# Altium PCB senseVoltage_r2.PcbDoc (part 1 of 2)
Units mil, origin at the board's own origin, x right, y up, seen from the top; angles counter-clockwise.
Board outline 4100 x 1400 mil, 2 copper layers (Top Layer, Bottom Layer), stack 62 mil thick; 83 components, 46 nets, 184 pads, 26 vias.
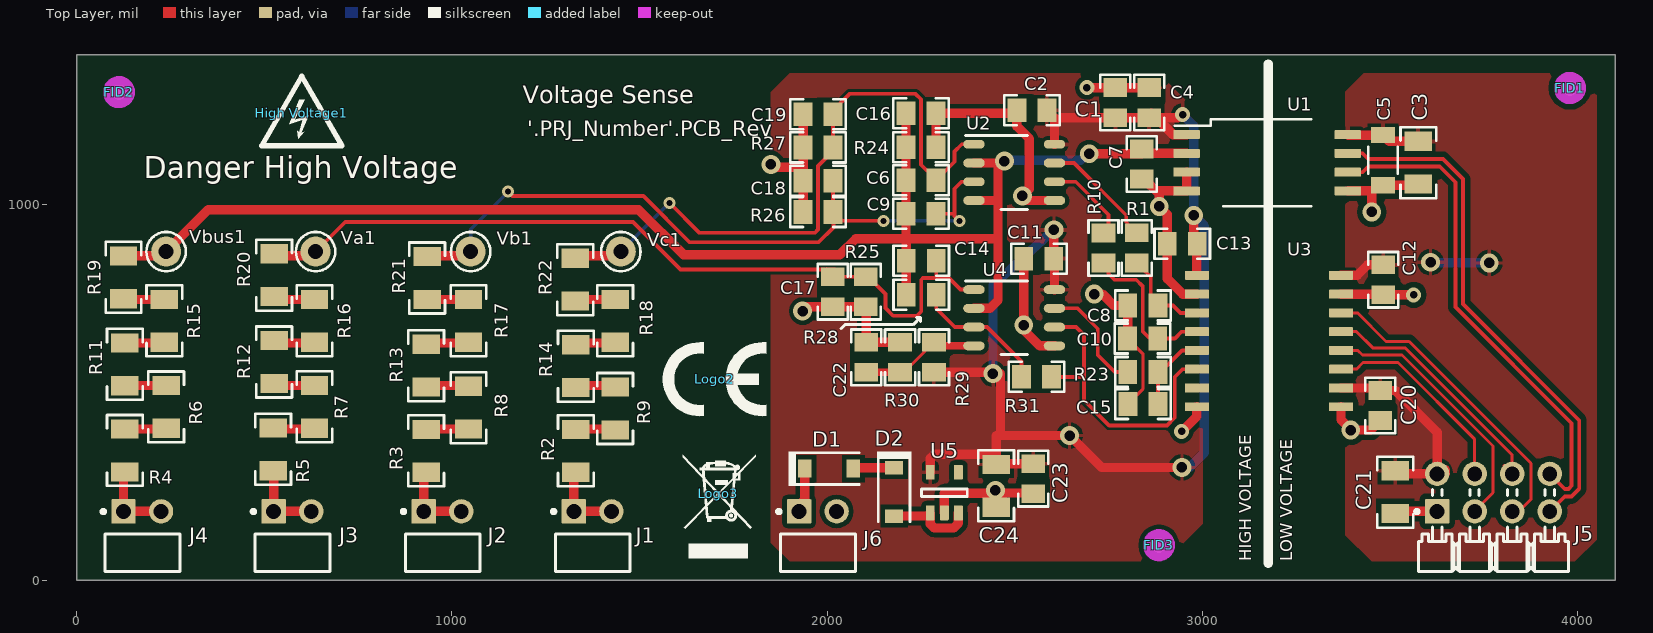
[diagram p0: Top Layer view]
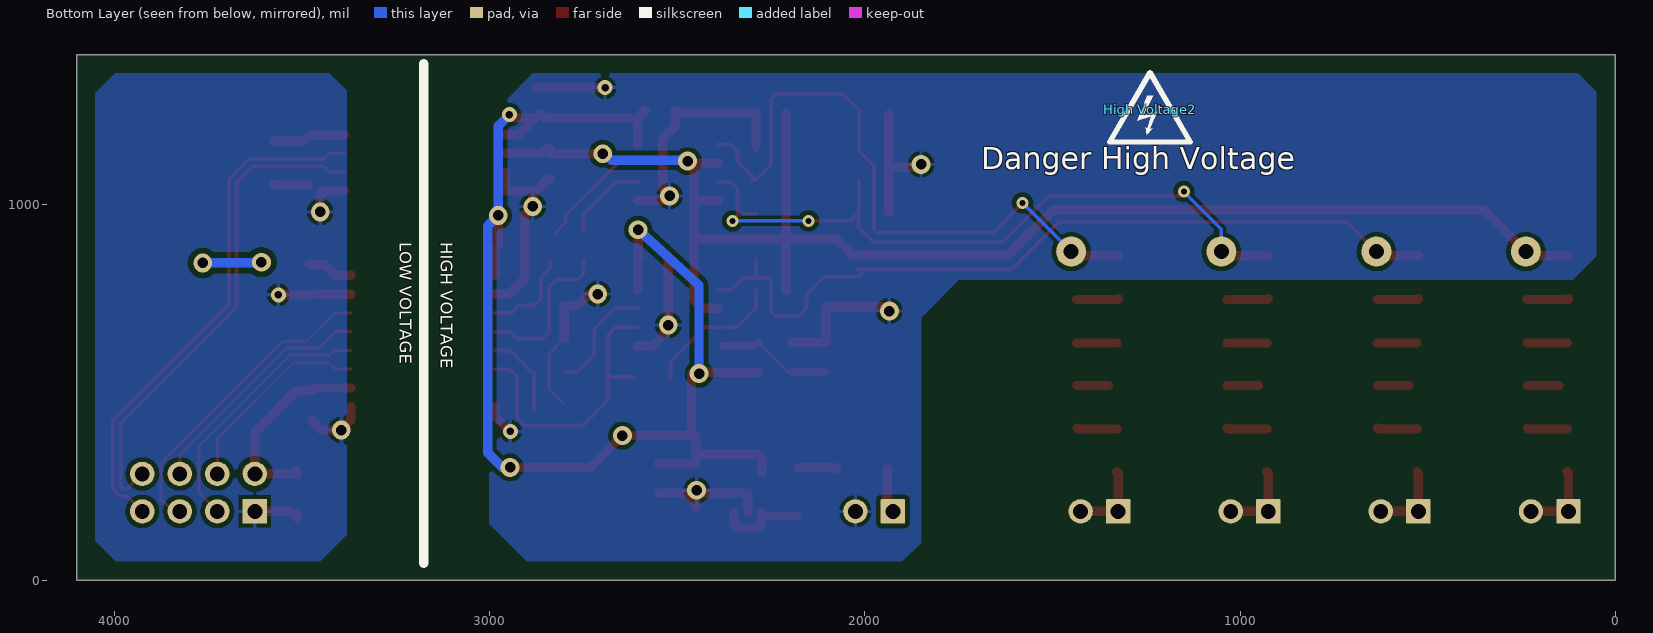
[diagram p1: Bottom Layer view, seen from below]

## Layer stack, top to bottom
Top Solder: solder mask 0.4, Solder Resist, Dk 3.5
Top Layer: signal copper 1.4
Dielectric1: core 59.2, FR-4, Dk 4.8
Bottom Layer: signal copper 1.4
Bottom Solder: solder mask 0.4, Solder Resist, Dk 3.5

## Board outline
0,0 4100,0 4100,1400 0,1400

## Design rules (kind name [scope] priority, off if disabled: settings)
AcuteAngle [All] p1: minimum=4.50000000000000E+0001 checktracksonly=FALSE
AssemblyTestPointUsage [All] p1: valid=2
BoardOutlineClearance BoardOutlineClearance_MountingHoles [OnCopper and InComponentClass('Mounting Holes')] p1: gap=39.37 ignorepadtopadclearanceinfootprint=FALSE
BoardOutlineClearance BoardOutlineClearance_Poly [OnCopper and IsPoly] p2: gap=25 ignorepadtopadclearanceinfootprint=FALSE
BoardOutlineClearance [OnCopper and Not InComponentClass('Logo') and not InComponentClass('FiducialMark') and not InRegion(1000,500,4000,800) and not InPoly and Not IsKeepOut] p3: gap=60 ignorepadtopadclearanceinfootprint=FALSE except(25: Poly-CutoutEdge Text-CutoutEdge; 50: Arc-CutoutEdge Track-CutoutEdge SMDPad-CutoutEdge THPad-CutoutEdge Via-CutoutEdge Fill-CutoutEdge Region-CutoutEdge)
Clearance Clearance_Keepouts [((IsTrack Or IsArc) And Not InPoly) And IsFree and IsKeepOut vs ((IsTrack Or IsArc) And Not InPoly) And IsFree and IsKeepOut] p1: gap=0 ignorepadtopadclearanceinfootprint=FALSE
Clearance Clearance_Small_Vias [(HoleDiameter = 10)] p2: gap=8 ignorepadtopadclearanceinfootprint=TRUE
Clearance Clearance_TP_blue_wires [HasFootprint('TP_H045P075')] p3: gap=15 ignorepadtopadclearanceinfootprint=TRUE
Clearance Clearance_3V3 [InNet('3V3')] p4: gap=15 ignorepadtopadclearanceinfootprint=TRUE
Clearance Clearance_10_mil_traces [Width = 10] p5: gap=8 ignorepadtopadclearanceinfootprint=TRUE
Clearance Clearance_Poly [InPolygon] p6: gap=12 ignorepadtopadclearanceinfootprint=TRUE
Clearance Clearance_FiducialMark [IsKeepOut and InComponentClass('FiducialMark') vs IsPad and InComponentClass('FiducialMark')] p7: gap=0 ignorepadtopadclearanceinfootprint=FALSE
Clearance [All] p8: gap=7.87 ignorepadtopadclearanceinfootprint=TRUE
ComponentClearance ComponentClearance_MountingHoles_FiducialMarks [InComponentClass('Mounting Holes') vs InComponentClass('FiducialMark')] p1: gap=50 collisioncheckmode=3 verticalgap=10 showdistances=FALSE
ComponentClearance ComponentClearance_Shunt [InComponentClass('Header') vs InComponentClass('Shunt')] p2: gap=0 collisioncheckmode=3 verticalgap=0 showdistances=FALSE
ComponentClearance ComponentClearance_Logo [InComponentClass('Logo')] p3: gap=50 collisioncheckmode=3 verticalgap=10 showdistances=FALSE
ComponentClearance ComponentClearance_ScrewToNut [(HasFootprint('NY PMS 440 0025 PH')) vs (HasFootprint('Keystone_1902C'))] p4: gap=5 collisioncheckmode=3 verticalgap=10 showdistances=FALSE
ComponentClearance ComponentClearance_MountingHoles [InComponentClass('Mounting Holes')] p5: gap=250 collisioncheckmode=3 verticalgap=100000 showdistances=FALSE
ComponentClearance ComponentClearance_SmallPassives [HasFootprint('0201*') or HasFootprint('0402*') or HasFootprint('0508') or HasFootprint('0603*') or HasFootprint('0612') or HasFootprint('0805*') or HasFootprint('0815*') or HasFootprint('0830*') or HasFootprint('1206*') or HasFootprint('1210*') or HasFootprint('1808*') or HasFootprint('1812*') or HasFootprint('1825*') or HasFootprint('2010*') or HasFootprint('2220*') or HasFootprint('2225*') or HasFootprint('2512*') or HasFootprint('2728*') or HasFootprint('3518*') vs HasFootprint('0201*') or HasFootprint('0402*') or HasFootprint('0508') or HasFootprint('0603*') or HasFootprint('0612') or HasFootprint('0805*') or HasFootprint('0815*') or HasFootprint('0830*') or HasFootprint('1206*') or HasFootprint('1210*') or HasFootprint('1808*') or HasFootprint('1812*') or HasFootprint('1825*') or HasFootprint('2010*') or HasFootprint('2220*') or HasFootprint('2225*') or HasFootprint('2512*') or HasFootprint('2728*') or HasFootprint('3518*')] p6: gap=14.96 collisioncheckmode=3 verticalgap=10 showdistances=FALSE
ComponentClearance ComponentClearance_THtoSMT [IsThruComponent vs IsSMTComponent] p7: gap=20 collisioncheckmode=3 verticalgap=30 showdistances=FALSE
ComponentClearance ComponentClearance_TestPoint [HasFootprint('TP_H045P075')] p8: gap=0 collisioncheckmode=3 verticalgap=30 showdistances=FALSE
ComponentClearance ComponentClearance_THtoTH [IsThruComponent vs IsThruComponent] p9: gap=30 collisioncheckmode=3 verticalgap=30 showdistances=FALSE
ComponentClearance [All] p10: gap=30 collisioncheckmode=3 verticalgap=10 showdistances=FALSE
DiffPairsRouting [All] p1: maxlimit=100 minlimit=10 mostfreqgap=10 toplayer_minwidth=10 toplayer_maxwidth=15 toplayer_prefwidth=10 bottomlayer_minwidth=10 bottomlayer_maxwidth=15 bottomlayer_prefwidth=10 maxuncoupledlength=1000
FabricationTestPointUsage TestPointUsage [All] p1: valid=2 allowmultiple=FALSE
FabricationTestpoint Testpoint [All] p1: side=3 testpointundercomponent=TRUE minsize=40 maxsize=100 preferedsize=60 minholesize=0 maxholesize=40 preferedholesize=32 testpointgrid=1 allowsidetop=TRUE allowsidebottom=TRUE usegrid=TRUE gridtolerance=0.01
FanoutControl Fanout_LCC [IsLCC] p1: bgadir=Out bgaviamode=Centered fanoutstyle=Auto fanoutdirection=Alternating viagrid=1 // Fanout_LCC (Default Rule)
FanoutControl Fanout_BGA [IsBGA] p2: bgadir=Out bgaviamode=Centered fanoutstyle=Auto fanoutdirection=Alternating viagrid=1 // Fanout_BGA (Default Rule)
FanoutControl Fanout_Default [All] p4: bgadir=Out bgaviamode=Centered fanoutstyle=Auto fanoutdirection=Alternating viagrid=1 // Fanout_Default (Default Rule)
FanoutControl Fanout_Small [(CompPinCount < 5)] p5: bgadir=Out bgaviamode=Centered fanoutstyle=Auto fanoutdirection=OutThenIn viagrid=1 // Fanout_Small (Default Rule)
HoleSize [All] p1: absolutevalues=TRUE maxlimit=251 minlimit=7.87 maxpercent=80.000 minpercent=20.000
MinimumAnnularRing MinimumAnnularRing_ThermalPadVias [IsVia and InAnyComponent] p1: minimumring=5.91
MinimumAnnularRing [All] p2: minimumring=6
MinimumSolderMaskSliver MinimumSolderMaskSliver_Logo [InComponentClass('Logo') vs InComponentClass('Logo')] p1: minsoldermaskwidth=0.7
MinimumSolderMaskSliver [All] p2: minsoldermaskwidth=3.94
PlaneConnect [All] p1: planeconnectstyle=Relief reliefexpansion=10 reliefentries=4 reliefconductorwidth=10 reliefairgap=10
PolygonConnect [All] p1: connectstyle=Relief reliefconductorwidth=10 reliefentries=4 polygonreliefangle="90 Angle" airgapwidth=10
RoomDefinition RoomDefinition_2 [False vs False] p1: confinementstyle=ConfineIn formatcopy=TRUE lockcomponents=FALSE outline 1180,-285 815,-285 815,955 1180,955
RoomDefinition RoomDefinition_3 [InComponentClass('Room Definition 4') vs False] p2: confinementstyle=ConfineIn formatcopy=TRUE lockcomponents=FALSE outline 1208,-284 1558,-284 1558,966 1208,966
RoomDefinition RoomDefinition_1 [InComponentClass('Room Definition 2') vs False] p3: confinementstyle=ConfineIn formatcopy=TRUE lockcomponents=FALSE outline 408,-284 758,-284 758,966 408,966
RoomDefinition [InComponentClass('Room Definition 1') vs False] p4: confinementstyle=ConfineIn formatcopy=TRUE lockcomponents=FALSE outline 8,-284 358,-284 358,966 8,966
RoutingVias ThermalPadVias [IsVia and InAnyComponent] p1: holewidth=7.87 width=19.68 viastyle="Through Hole" minholewidth=7.87 minwidth=19.68 maxholewidth=12.99 maxwidth=23.62
RoutingVias [All] p2: holewidth=16 width=34 viastyle="Through Hole" minholewidth=7.87 minwidth=22 maxholewidth=40 maxwidth=65
SilkToBoardRegionClearance [Not ((IsComment or IsDesignator) And (Hide <> 'False')) and not InRegion(1000,500,4000,800)] p1:
SilkToSilkClearance SilkToSilkClearance_Pb-FreeLogo [(HasFootprint('Pb-Free_Overlay_Medium') OR HasFootprint('Pb-Free_Overlay_Small')) vs (HasFootprint('Pb-Free_Overlay_Medium') OR HasFootprint('Pb-Free_Overlay_Small'))] p1: silktosilkclearance=0
SilkToSilkClearance [All] p2: silktosilkclearance=3.94
SilkToSolderMaskClearance SilkToComponentPadClearance [(IsPad or IsFill or IsRegion) and InAnycomponent] p1: minsilkscreentomaskgap=5 clearancetoexposedcopper=TRUE
SilkToSolderMaskClearance "Silk to Solder Mask Opening" [All] p2: minsilkscreentomaskgap=3 clearancetoexposedcopper=FALSE
SolderMaskExpansion [All] p1: expansion=1.97
UnRoutedNet [All] p1: checkbadconnections=TRUE
Width [All] p1: maxlimit=100 minlimit=6 preferedwidth=10 checkconnectedcopper=TRUE
14 further rules are at their usual default settings.

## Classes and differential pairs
component class voltageSense_EVT: C1 C2 C3 C4 C5 C6 C7 C8 C9 C10 C11 C12 C13 C14 C15 C16 C17 C18 C19 C20 C21 C22 C23 C24 D1 D2 J1 J2 J3 J4 J5 J6 R1 R2 R3 R4 R5 R6 R7 R8 R9 R10 R11 R12 R13 R14 R15 R16 R17 R18 R19 R20 R21 R22 R23 R24 R25 R26 R27 R28 R29 R30 R31 U1 U2 U3 U4 U5 Va1 Vb1 Vbus1 Vc1
component class Header: J5
component class Hardware: FID1 FID2 FID3 "High Voltage1" "High Voltage2" Logo2 Logo3 ZZ1 ZZ2 ZZ3 ZZ4
component class FiducialMark: FID1 FID2 FID3
component class AssemblyNote: ZZ1 ZZ2 ZZ3 ZZ4
differential pair Vdc: +Vdc_P -Vdc_N

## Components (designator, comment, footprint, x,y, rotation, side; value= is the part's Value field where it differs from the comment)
C1 "GRM219R71C225KE15" 0805_HV 2767.56,1271.99 r90 top value=2.2uF
C2 "08053C224JAT2A" 0805_HV 2545.36,1251.65 r0 top value=0.22uF
C3 "GRM31MR71C225KA35L" 1206 3575,1112.09 r90 top value=2.2uF
C4 "08053C224JAT2A" 0805_HV 2857.85,1271.99 r90 top value=0.22uF
C5 "C1206H104J3GACTU" 1206_190 3480.78,1118.5 r90 top value=0.1uF
C6 "08051A150JAT2A" 0805_HV 2249.86,1065.2 r180 top value=15pF
C7 "08051A100CAT2A" 0805_HV 2837.85,1108.49 r270 top value=10pF
C8 "08051A101JAT2A" 0805_HV 2840.95,731.4 r180 top value=100pF
C9 "08051A150JAT2A" 0805_HV 2249.86,975.68 r180 top value=15pF
C10 "08051A101JAT2A" 0805_HV 2840.36,643.68 r180 top value=100pF
C11 "08053C224JAT2A" 0805_HV 2563.81,855.84 r0 top value=0.22uF
C12 "GRM219R71C104KA01D" 0805_HV 3481.58,800 r270 top value=0.1uF
C13 "GRM219R71C104KA01D" 0805_HV 2946,895.58 r180 top value=0.1uF
C14 "08051A150JAT2A" 0805_HV 2250.39,850.42 r180 top value=15pF
C15 "08051A101JAT2A" 0805_HV 2841.38,468.91 r180 top value=100pF
C16 "08053C224JAT2A" 0805_HV 2249.86,1243.74 r180 top value=0.22uF
C17 "08051A330JAT2A" 0805_HV 2015,768.2 r270 top value=33pF
C18 "08051A330JAT2A" 0805_HV 1975.59,1063.84 r180 top value=33pF
C19 "08051A330JAT2A" 0805_HV 1975.59,1241.49 r180 top value=33pF
C20 "GRM21BR70J106KE76L" 0805_HV 3473.12,465 r90 top value=10uF
C21 "1206YC104KAT2A" 1206 3513.32,234.06 r270 top value=0.1uF
C22 "08051A330JAT2A" 0805_HV 2104.05,593.42 r90 top value=33pF
C23 "GRM21BR70J106KE76L" 0805_HV 2549,270 r90 top value=10uF
C24 "1206YC104KAT2A" 1206 2450,251 r270 top value=0.1uF
D1 "MMSZ4687-HE3-08" SOD-123 2005,297 r0 top value=4.3V
D2 "MMSZ4687-HE3-08" SOD-123 2178,235 r270 top value=4.3V
FID1 "Fiducial" Fiducial10-20#1 3978.96,1310.98 r90 top
FID2 "Fiducial" Fiducial10-20#2 112.82,1300 r0 top
FID3 "Fiducial" Fiducial10-20#2 2883.67,92.88 r0 top
"High Voltage1" "DANGER HIGH VOLTAGE" IEC_HighVoltage_Small 600,1245 r0 top
"High Voltage2" "DANGER HIGH VOLTAGE" IEC_HighVoltage_Small 1240,1255 r180 bottom
J1 "TSW-102-08-G-S-RA" TSW-102-08-G-S-RA 1375,182.88 r0 top
J2 "TSW-102-08-G-S-RA" TSW-102-08-G-S-RA 975,182.88 r0 top
J3 "TSW-102-08-G-S-RA" TSW-102-08-G-S-RA 575,182.88 r0 top
J4 "TSW-102-08-G-S-RA" TSW-102-08-G-S-RA 175,182.88 r0 top
J5 "TSW-104-09-G-D-RA" Samtec_TSW-104-09-G-D-RA 3775,232.88 r0 top
J6 "TSW-102-08-G-S-RA" TSW-102-08-G-S-RA 1975,182.88 r0 top
Logo2 "CE Mark" CE_Mark_5mm 1700,535 r0 top
Logo3 "WEEE logo" WEEE_Minimum 1710,229.9 r0 top
R1 "PHT0805Y1001BGT200" 0805_HV 2824.67,885 r270 top value=1.00k
R2 "ERJ-8ENF2003V" 1206 1330.34,344.22 r270 top value=200k
R3 "ERJ-8ENF2003V" 1206 931.43,344.22 r270 top value=200k
R4 "ERJ-8ENF2003V" 1206 128.57,345.23 r270 top value=200k
R5 "ERJ-8ENF2003V" 1206 523.58,348.23 r270 top value=200k
R6 "ERJ-8ENF2003V" 1206 238.6,461.3 r270 top value=200k
R7 "ERJ-8ENF2003V" 1206 634,461.39 r270 top value=200k
R8 "ERJ-8ENF2003V" 1206 1044.24,459.33 r270 top value=200k
R9 "ERJ-8ENF2003V" 1206 1435,456.98 r270 top value=200k
R10 "PHT0805Y1001BGT200" 0805_HV 2735.98,885 r270 top value=1.00k
R11 "ERJ-8ENF2003V" 1206 128.57,574.58 r270 top value=200k
R12 "ERJ-8ENF2003V" 1206 526.26,580.99 r270 top value=200k
R13 "ERJ-8ENF2003V" 1206 931.43,571.15 r270 top value=200k
R14 "ERJ-8ENF2003V" 1206 1330.34,569.88 r270 top value=200k
R15 "ERJ-8ENF2003V" 1206 234,690.51 r270 top value=200k
R16 "ERJ-8ENF2003V" 1206 634,690.51 r270 top value=200k
R17 "ERJ-8ENF2003V" 1206 1044.24,690.72 r270 top value=200k
R18 "ERJ-8ENF2003V" 1206 1435,690.51 r270 top value=200k
R19 "ERJ-8ENF2003V" 1206 125,806.65 r270 top value=200k
R20 "ERJ-8ENF2003V" 1206 526.26,812.29 r270 top value=200k
R21 "ERJ-8ENF2003V" 1206 934.1,804.68 r270 top value=200k
R22 "ERJ-8ENF2003V" 1206 1328.67,800.19 r270 top value=200k
R23 "PHT0805Y1001BGT200" 0805_HV 2840.95,554.41 r0 top value=1.00k
R24 "RG2012P-302-B-T5" 0805_HV 2249.86,1153.35 r180 top value=3.00k
R25 "RG2012P-432-B-T5" 0805_HV 2103,768.2 r90 top value=4.30k
R26 "RG2012P-432-B-T5" 0805_HV 1975.59,980.54 r0 top value=4.30k
R27 "RG2012P-432-B-T5" 0805_HV 1975.59,1152.62 r0 top value=4.30k
R28 "RG2012P-302-B-T5" 0805_HV 2250.39,760 r180 top value=3.00k
R29 "RR1220P-3321-D-M" 0805_HV 2284.44,593.42 r270 top value=3.32k
R30 "RG2012P-3322-B-T5" 0805_HV 2194.05,593.42 r270 top value=33.2k
R31 "RR1220P-104-D" 0805_HV 2557.79,541.24 r180 top value=100k
U1 "AMC1311BDWVR" DWV0008A 3171.97,1111.83 r0 top
U2 "TLV3502AID" D0008A_N 2498.14,1086.18 r0 top
U3 "ISO7240CDWR" DW0016B_HV 3176.97,636.82 r0 top
U4 "TLV3502AID" D0008A_N 2498.09,698.92 r0 top
U5 "TLV71333PQDBVRQ1" DBV0005A_N 2312,233 r90 top
Va1 "5002" Keystone5002 636.76,875 r270 top
Vb1 "5002" Keystone5002 1050,875 r90 top
Vbus1 "5002" Keystone5002 238.6,875 r270 top
Vc1 "5002" Keystone5002 1450,875 r180 top
ZZ1 "This Assembly Note is for PCB labels only" AssemblyNoteLabel 155,5443 r0 top
ZZ2 "These assemblies are ESD sensitive, ESD precautions shall be observed." AssemblyNote 155,5334.11 r0 top
ZZ3 "These assemblies must be clean and free from flux and all contaminants. Use of no clean flux is not acceptable." AssemblyNote 155,5245.56 r0 top
ZZ4 "These assemblies must comply with workmanship standards IPC-A-610 Class 2, unless otherwise specified." AssemblyNote 155,5157 r0 top

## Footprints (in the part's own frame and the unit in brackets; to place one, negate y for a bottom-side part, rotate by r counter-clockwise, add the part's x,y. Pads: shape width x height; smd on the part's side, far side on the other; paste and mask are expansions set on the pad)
0805_HV [mil] "0805 with 30mil clearance between pads"
  rect 50x63 smd: 1(-40,0) 2(40,0)
  silkscreen extent -74,-40 74,40, body extent -43,-29 43,29, height 57
1206 [mm] "1206 from SM-752 data"
  rect 1.3x1.85 smd: 1(-1.45,0) 2(1.45,0)
  silkscreen extent -2.4,-1.21 2.4,1.21, body extent -1.7,-0.9 1.7,0.9, height 1.35
1206_190 [mm] "1206_190"
  rect 1.1x1.6 smd: 1(-1.7,0) 2(1.7,0)
  silkscreen extent -0.9,-1 0.9,1, body extent -1.75,-0.95 1.75,0.95, height 1.9
AssemblyNote [mil] "Assembly Note"
AssemblyNoteLabel [mil] "Assembly Note for PCB Labels"
CE_Mark_5mm [mil] "Minimum text height for CE Mark"
  silkscreen extent -138,-98 138,98
D0008A_N [mm] "SOIC, 8-Leads, Body 4.9x3.9mm, Pitch 1.27mm, IPC Medium Density"
  oval 1.45x0.6 smd: 1(-2.725,1.905) 2(-2.725,0.635) 3(-2.725,-0.635) 4(-2.725,-1.905) 5(2.725,-1.905) 6(2.725,-0.635) 7(2.725,0.635) 8(2.725,1.905)
  silkscreen extent -3.3,-2.5 0.9,2.5, body extent -3,-2.45 3,2.45, height 1.63
DBV0005A_N [mm] "SOT23, 5-Leads, Body 2.9x1.6mm, Pitch 0.95mm, Lead Span 2.8mm, IPC Medium Density"
  rrect17% 1x0.6 smd: 1(-1.375,0.95) 2(-1.375,0) 3(-1.375,-0.95) 4(1.375,-0.95) 5(1.375,0.95)
  silkscreen extent -0.25,-1.55 0.25,1.55, body extent -1.42,-1.46 1.42,1.46, height 1.09
DW0016B_HV [mm] "SOIC-16, HV/isolation option"
  rrect17% 1.65x0.6 smd: 1(-4.875,4.445) 2(-4.875,3.175) 3(-4.875,1.905) 4(-4.875,0.635) 5(-4.875,-0.635) 6(-4.875,-1.905) 7(-4.875,-3.175) 8(-4.875,-4.445) 9(4.875,-4.445) 10(4.875,-3.175) 11(4.875,-1.905) 12(4.875,-0.635) 13(4.875,0.635) 14(4.875,1.905) 15(4.875,3.175) 16(4.875,4.445)
  body extent -5.17,-5.15 5.17,5.15, height 2.59
DWV0008A [mm] "SOIC, 8-Leads, Body 5.95x7.6mm (max), Pitch 1.27mm"
  rrect17% 1.8x0.6 smd: 1(-5.45,1.905) 2(-5.45,0.635) 3(-5.45,-0.635) 4(-5.45,-1.905) 5(5.45,-1.905) 6(5.45,-0.635) 7(5.45,0.635) 8(5.45,1.905)
  silkscreen extent -6.25,-2.95 2.98,2.95, body extent -5.77,-2.92 5.77,2.93, height 2.67
Fiducial10-20#1 [mm]
  round 1 smd mask+0.5: 1(-0.025,0)
  Top Layer keep-out circle w1.178: c0,0 r0.5
Fiducial10-20#2 [mm]
  round 1 smd mask+0.5: 1(0,0)
  Top Layer keep-out circle w1.178: c0,0 r0.5
IEC_HighVoltage_Small [mil]
  silkscreen extent -107,-88 107,97
Keystone5002 [mil] "For Keystone 500x miniature loop terminals"
  round 80 hole 40: 1(0,0)
  silkscreen extent -52,-52 52,52, body extent -49,-49 49,49, height 182
Samtec_TSW-104-09-G-D-RA [mm] "Samtec Right Angle Header"
  rrect6% 1.65x1.65 / inner rect 1.65x1.65 / far side rect 1.65x1.65 hole 1: 1(-3.81,-1.27)
  round 1.65 hole 1: 2(-3.81,1.27) 3(-1.27,-1.27) 4(-1.27,1.27) 5(1.27,-1.27) 6(1.27,1.27) 7(3.81,-1.27) 8(3.81,1.27)
  silkscreen extent -5.3,-5.33 5.08,0.2, body extent -5.08,-11.18 5.08,1.59, height 5.51
SOD-123 [mm] "On Semi recommended land pattern"
  rect 0.915x1.22 smd: 1(-1.637,0) 2(1.637,0)
  silkscreen extent -2.74,-1.17 2.03,1.17, body extent -1.93,-0.9 1.93,0.9, height 1.35
TSW-102-08-G-S-RA [mm] "Samtec Right Angle Header"
  rrect6% 1.65x1.65 hole 1: 1(-1.27,0)
  round 1.65 hole 1: 2(1.27,0)
  silkscreen extent -2.76,-4.06 2.54,0.11, body extent -2.54,-9.91 2.54,0.32, height 3.05
WEEE_Minimum [mil] "WEEElie bin"
  silkscreen extent -95,-172 99,104

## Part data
C1: library part CMP-0008211-2, "CAP, CERM, 2.2 uF, 16 V, +/- 10%, X7R, 0805", Cap_Case=0805, Manufacturer=MuRata, TempCo=X7R, Tolerance_%=10%, Value1=Unknown, Value2=16V, ValueDisplayed=2.2uF
C2 C4 C11 C16: library part CMP-0007570-1, "CAP, CERM, 0.22 uF, 25 V, +/- 5%, X7R, 0805", Cap_Case=0805, Manufacturer=AVX, Supplier Part Number 1=478-3756-1-ND, TempCo=X7R, Tolerance_%=5%, Value1="0.016 ohm", Value2=25V, ValueDisplayed=0.22uF
C3: library part CMP-0008987-1, "CAP, CERM, 2.2 uF, 16 V, +/- 10%, X7R, 1206", Cap_Case=1206, Manufacturer=MuRata, Supplier Part Number 1=81-GRM426X225K16L, TempCo=X7R, Tolerance_%=10%, Value1="0.006 ohm", Value2=16V, ValueDisplayed=2.2uF
C5: library part CMP-0008641-1, "CAP, CERM, 0.1 uF, 25 V, +/- 5%, C0G/NP0, 1206_190", Cap_Case=1206, Manufacturer=Kemet, Supplier Part Number 1=399-5750-1-ND, TempCo=C0G/NP0, Tolerance_%=5%, Value1=Unknown, Value2=25V
C6 C9 C14: library part CMP-0007520-1, "CAP, CERM, 15 pF, 100 V, +/- 5%, C0G/NP0, 0805", Cap_Case=0805, Manufacturer=AVX, Supplier Part Number 1=478-1279-1-ND, TempCo=C0G/NP0, Tolerance_%=5%, Value1="1.185 ohm", Value2=100V, ValueDisplayed=15pF
C7: library part CMP-0007513-1, "CAP, CERM, 10 pF, 100 V, +/- 5%, C0G/NP0, 0805", Cap_Case=0805, Manufacturer=AVX, Supplier Part Number 1=478-3730-1-ND, TempCo=C0G/NP0, Tolerance_%=5%, Value1="1.561 ohm", Value2=100V, ValueDisplayed=10pF
C8 C10 C15: library part CMP-0007517-1, "CAP, CERM, 100 pF, 100 V, +/- 5%, C0G/NP0, 0805", Cap_Case=0805, Manufacturer=AVX, Supplier Part Number 1=478-1284-1-ND, TempCo=C0G/NP0, Tolerance_%=5%, Value1="0.356 ohm", Value2=100V, ValueDisplayed=100pF
C12 C13: library part CMP-0008209-1, "CAP, CERM, 0.1 uF, 16 V, +/- 10%, X7R, 0805", Cap_Case=0805, Manufacturer=MuRata, Supplier Part Number 1=490-1683-1-ND, TempCo=X7R, Tolerance_%=10%, Value1=Unknown, Value2=16V, ValueDisplayed=0.1uF
C17 C18 C19 C22: library part CMP-0007529-1, "CAP, CERM, 33 pF, 100 V, +/- 5%, C0G/NP0, 0805", Cap_Case=0805, Manufacturer=AVX, Supplier Part Number 1=478-1281-1-ND, TempCo=C0G/NP0, Tolerance_%=5%, Value1="0.708 ohm", Value2=100V, ValueDisplayed=33pF
C20 C23: library part CMP-0008311-2, "CAP, CERM, 10 uF, 6.3 V, +/- 10%, X7R, 0805", Cap_Case=0805, Manufacturer=MuRata, Supplier Part Number 1=490-3904-1-ND, TempCo=X7R, Tolerance_%=10%, Value1=Unknown, Value2=6.3V, ValueDisplayed=10uF
C21 C24: library part CMP-0860522-1, "CAP, CERM, 0.1 µF, 16 V,+/- 10%, X7R, 1206", Cap_Case=1206, Manufacturer=AVX, TempCo=X7R, Tolerance_%=10%, Value2=16V, ValueDisplayed=0.1µF
D1 D2: library part CMP-0077560-1, "Diode, Zener, 4.3 V, 500 mW, AEC-Q101, SOD-123", Manufacturer=Vishay-Semiconductor, Power_W=500mW, Supplier Part Number 1=MMSZ4687-HE3-08-ND, Value1=0.5W
FID1 FID2 FID3: library part CMP-0077181-1, "Fiducial mark.  There is nothing to buy or mount.", Manufacturer=N/A
"High Voltage1" "High Voltage2": library part CMP-0074835-1, "IEC 61010-1 High Voltage Warning"
J1 J2 J3 J4 J6: library part CMP-0055976-1, "Header, 100mil, 2x1, Gold, R/A, TH", Color=Black, Current_A=6.3A, Manufacturer=Samtec, Supplier Part Number 1=SAM1039-02-ND, Voltage_V=550V
J5: library part CMP-0075584-1, "Header, 100mil, 4x2, Gold, R/A, TH", Color=Black, Current_A=6.3A, Manufacturer=Samtec, Supplier Part Number 1=79P5069, Voltage_V=550V
Logo2: library part CMP-0074844-1
Logo3: library part CMP-0074769-1
R1 R10 R23: library part CMP-0018844-1, "RES, 1.00 k, 0.1%, 0.06 W, 0805", Manufacturer="Vishay Sfernice", Power_W=60mW, Supplier Part Number 1=PHTD-1.0KCT-ND, TempCo="15 ppm/C", Tolerance_%=0.1%, Value2=0.06W, Value_Code=1k00, ValueDisplayed=1.00k
R2 R3 R4 R5 R6 R7 R8 R9 R11 R12 R13 R14 R15 R16 R17 R18 R19 R20 R21 R22: library part CMP-0017437-3, "RES, 200 k, 1%, 0.25 W, AEC-Q200 Grade 0, 1206", Manufacturer=Panasonic, Power_W=250mW, Supplier Part Number 1=P200KFCT-ND, TempCo="100 ppm/C", Tolerance_%=1%, Value2=0.25W, Value_Code=200k
R24 R28: library part CMP-0018951-1, "RES, 3.00 k, 0.1%, 0.125 W, 0805", Manufacturer="Susumu Co Ltd", Power_W=125mW, Supplier Part Number 1=RG20P3.0KBCT-ND, TempCo="25 ppm/C", Tolerance_%=0.1%, Value2=0.125W, Value_Code=3k00, ValueDisplayed=3.00k
R25 R26 R27: library part CMP-0018983-1, "RES, 4.30 k, 0.1%, 0.125 W, 0805", Manufacturer="Susumu Co Ltd", Power_W=125mW, Supplier Part Number 1=RG20P4.3KBCT-ND, TempCo="25 ppm/C", Tolerance_%=0.1%, Value2=0.125W, Value_Code=4k30, ValueDisplayed=4.30k
R29: library part CMP-0019250-1, "RES, 3.32 k, 0.5%, 0.1 W, 0805", Manufacturer="Susumu Co Ltd", Power_W=100mW, Supplier Part Number 1=RR12P3.32KDCT-ND, TempCo="25 ppm/C", Tolerance_%=0.5%, Value2=0.1W, Value_Code=3k32, ValueDisplayed=3.32k
R30: library part CMP-0018959-1, "RES, 33.2 k, 0.1%, 0.125 W, 0805", Manufacturer="Susumu Co Ltd", Power_W=125mW, Supplier Part Number 1=RG20P33.2KBCT-ND, TempCo="25 ppm/C", Tolerance_%=0.1%, Value2=0.125W, Value_Code=33k2, ValueDisplayed=33.2k
R31: library part CMP-0019096-1, "RES, 100 k, 0.5%, 0.1 W, 0805", Manufacturer="Susumu Co Ltd", Power_W=100mW, Supplier Part Number 1=RR12P100KDCT-ND, TempCo="25 ppm/C", Tolerance_%=0.5%, Value2=0.1W, Value_Code=100k
U1: library part CMP-0078341-1, "Precision, 2-V Input, Reinforced Isolated Amplifier, DWV0008A (SOIC-8)", Alternate Manufacturer="Texas Instruments", Alternate PartNumber=AMC1311BDWV
U2 U4: library part CMP-0065423-1, "4.5ns Rail-to-Rail Comparator, D0008A (SOIC-8)", Alternate Manufacturer="Texas Instruments"
U3: library part CMP-0029379-2, "2.5 kVrms, 25 Mbps, 4-Channel 4/0 Digital Isolator, DW0016B (SOIC-16)", Insulation Rating(VRMS)=2500, Manufacturer="Texas Instruments", Operating Temperature Range="-40 to 125 C", Rating=Catalog, Supply Voltage(s)(V)="3.3, 5"
U5: library part CMP-0073750-1, "Capacitor-Free, 150-mA, LDO Regulator w/ Foldback Current Limit, DBV0005A (SOT-23-5)", Alternate Manufacturer="Texas Instruments"
Va1 Vb1 Vbus1 Vc1: library part CMP-0055139-1, "Test Point, Miniature, White, TH", Color=White, Manufacturer=Keystone, Supplier Part Number 1=36-5002-ND
ZZ1: library part CMP-0003616-3
ZZ2: library part CMP-0077236-1
ZZ3: library part CMP-0077237-1
ZZ4: library part CMP-0077238-1

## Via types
v1: diameter 50, hole 28, Top Layer to Bottom Layer, 18 vias
v2: diameter 32, hole 16, Top Layer to Bottom Layer, 4 vias
v3: diameter 40, hole 20, Top Layer to Bottom Layer, 4 vias

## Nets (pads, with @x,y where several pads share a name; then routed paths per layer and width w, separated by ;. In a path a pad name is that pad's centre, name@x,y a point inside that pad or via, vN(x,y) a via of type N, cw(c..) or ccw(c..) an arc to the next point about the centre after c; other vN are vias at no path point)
3V3: C3.2 C5.2 C12.1 C20.2 C21.1 J5.2 U1.8 U3.10 U3.16 | length 1032.7
  Top Layer w25: U3.10@3368.9,511.82 3466.3,511.82 C20.2@3473.12,505 3513.83,505 3625,393.83 J5.2@3625,282.88 3516.24,282.88 3513.32,279.97 C21.1@3513.32,291.15 ; U3.16@3368.9,811.82 3412.25,811.82 3440.42,840 C12.1@3481.58,840 ; U1.8@3386.53,1186.83 3387.93,1185.43 C5.2@3480.78,1185.43 3497.04,1169.17 C3.2@3575,1169.17 ; v1(3607.5,847) v1@3610.34,844.16 ; J5.2@3646.17,282.88 J5.2@3646.17,294.21
  Bottom Layer w25: v1(3607.5,847) 3609.66,847 3611.66,845 v1(3763.85,845)
DGND: C3.1 C5.1 C12.2 C20.1 C21.2 J5.1 U1.5 U3.9 U3.15 | length 667.8
  Top Layer w25: U3.9@3368.9,461.82 3368.9,427.14 v1@3382.66,413.37 ; U3.15@3368.9,761.82 C12.2@3463.23,761.82 ; U1.5@3386.53,1036.83 3445,1036.83 3451.01,1030.82 v1(3451.01,980.68) v1@3446.01,975.68 ; v1(3395,399.73) 3447.85,399.73 C20.1@3473.12,425 ; C5.1@3480.78,1051.57 3571.57,1051.57 C3.1@3575,1055 ; C12.2@3481.58,760 3550,760 3550.05,759.95 v3(3562.5,759.95) ; C21.2@3513.32,176.97 3513.32,165.8 3530.41,182.88 J5.1@3625,182.88
HV_3V3: C1.1 C2.2 C4.1 C11.2 C13.1 C23.2 C24.1 R29.2 U1.1 U2.8 U3.1 U4.8 U5.5 | length 3543.6
  Top Layer w25: U5.5@2274.6,287.13 2274.6,324.6 2285,335 2450,335 ; R29.2@2284.44,553.42 v1@2425.58,553.42 ; v1@2438.34,553.42 v1(2441.64,550.11) ; 2461.64,385 v1@2461.64,550.11 ; C23.2@2549,310 2451.91,310 C24.1@2450,308.09 2450,335 ; C2.2@2585.36,1251.65 2605.42,1231.59 U2.8@2605.42,1161.18 ; C11.2@2601.1,858.55 C11.2@2603.81,855.84 2605.37,854.28 U4.8@2605.37,773.92 ; C11.2@2603.93,858.57 v1(2603.93,933.33) ; 2625.42,1231.59 2851.47,1231.59 C4.1@2863.81,1243.93 ; C4.1@2876.8,1230.94 2920.91,1186.83 U1.1@2957.4,1186.83 ; C4.1@2877.85,1231.99 2933.53,1231.99 2941.31,1239.77 v3(2946.59,1239.77) ; v1(2945,300) 2731.22,300 2646.22,385 v1(2645.58,385) 2450,384 2450,335 ; v1(2976.37,971.57) 2976.37,894.59 2985.04,885.92 U3.1@2985.04,811.82
  Bottom Layer w25: v1(2441.64,550.11) 2441.64,773.85 2442.21,785.98 v1(2603.93,933.33) ; v1(2945,300) 2965.44,300 3005,339.56 3005,942.95 v1(2976.37,971.57) 2988.07,971.57 2976.37,983.27 2976.37,1209.99 v3(2946.59,1239.77)
HV_GND: C1.2 C2.1 C4.2 C7.2 C8.2 C10.2 C11.1 C13.2 C15.2 C16.1 C17.2 C18.2 C19.2 C22.2 C23.1 C24.2 J6.2 R24.1 R25.1 R26.1 R27.1 R30.1 U1.3 U1.4 U2.5 U3.2 U3.8 U4.5 U5.2 | length 3152.7
  Top Layer w8: C10.2@2800.36,643.68 2840.95,603.09 2840.95,508.49 C15.2@2801.38,468.91
  Top Layer w25: v1(1850,1107.34) 1857.34,1100 1935.59,1100 ; v1@1929.45,728.2 v1@1934.45,728.2 ; v1(1934.45,716.76) v1@1934.45,728.2 ; C19.2@1935.59,1241.49 R27.1@1935.59,1152.62 1935.59,1100 ; R26.1@1936.54,979.59 R26.1@1935.59,980.54 C18.2@1935.59,1063.84 1935.59,1100 ; R25.1@2103,728.2 2018,728.2 C17.2@2015,728.2 v1@1934.45,728.2 ; R25.1@2104.05,712.62 C22.2@2104.05,633.42 R30.1@2194.05,633.42 ; R24.1@2289.86,1153.35 C16.1@2289.86,1243.74 2497.45,1243.74 C2.1@2505.36,1251.65 2505.36,1209.24 2538.42,1176.19 2538.42,1041.83 v1(2520,1023.41) 2532.24,1011.18 U2.5@2605.42,1011.18 ; U5.2@2312,178.87 2312,231.31 2450,231.31 C24.2@2450,206.4 ; C24.2@2450,193.91 C24.2@2450,206.4 ; C11.1@2523.81,855.84 2523.81,679.43 v1(2523.62,679.24) 2523.62,666.32 2566.01,623.92 U4.5@2605.37,623.92 ; C23.1@2549,232 2475.6,232 C24.2@2450,206.4 ; v1(2711.31,761.82) 2733.18,761.82 2763.6,731.4 C8.2@2800.95,731.4 2800.95,644.27 C10.2@2800.36,643.68 ; 2711.84,1311.99 C1.2@2767.56,1311.99 C4.2@2857.85,1311.99 C4.2@2877.85,1311.99 ; C7.2@2837.85,1068.49 2843.85,1068.49 2884.68,1027.65 ; v3(2944.38,396.03) 2985.04,436.68 U3.8@2985.04,461.82 ; U1.3@2957.4,1086.83 U1.4@2957.4,1036.83 2884.68,1036.83 2884.68,1027.65 ; U3.2@2985.04,761.82 2947.24,761.82 2906,803.06 C13.2@2906,895.58 2906,973.96 v1(2884.68,995.27) 2884.68,1027.65
  other v1: 2447.99,239.03
  other v3: 2691.84,1311.99
NetC6_1: C6.1 C19.1 R22.1 R27.2 U2.1 Vc1.1 | length 1747.9
  Top Layer w10: v2(1580,1005) 1660,925 1966.67,925 1975.66,933.99 1975.66,1103.28 2015.59,1143.21 R27.2@2015.59,1152.62 C19.1@2015.59,1241.49 2015.59,1251.54 2059.42,1295.37 2235.38,1295.37 2249.86,1280.89 2249.86,1106.26 2290.39,1065.73 2301.13,1065.73 2295.76,1071.1 2338.99,1114.33 2338.99,1141.65 2358.52,1161.18 U2.1@2390.86,1161.18
  Top Layer w25: R22.1@1325,863.73 1427.33,863.73 Vc1.1@1454.2,890.6
  Bottom Layer w10: Vc1.1@1450,875 v2(1580,1005)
